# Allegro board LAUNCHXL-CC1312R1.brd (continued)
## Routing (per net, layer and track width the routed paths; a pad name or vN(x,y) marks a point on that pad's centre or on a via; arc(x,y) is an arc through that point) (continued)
VBUS_DET: length 7.3
  TOP w0.15: R116.1 R115.1 10.14,83.85 9.65,84.34 v1(9.65,84.9) ; v1(9.65,89) U5.12
  BOTTOM w0.15: v1(9.65,84.9) v1(9.65,89)
VDD_SWITCH: length 93.7
  TOP w0.15: 35.85,111.8 35.6,111.55 v1(35.6,110.7) ; 35.85,111.8 35.7,111.95 U25.1 ; 35.85,111.8 C145.1
  TOP w0.201: U24.14 43.4,106.95 C144.1
  TOP w0.3: U27.5 4.19,86.32 4.46,86.05 v1(5,86.05) R136.1 ; U26.1 35.57,115.95 36.27,115.25 ; v1(35.67,115.1) 35.82,115.25 36.27,115.25 ; 36.27,115.25 C146.1 ; v1(44,106.3) 43.85,106.45 43.85,106.5 C144.1
  L3 w0.3: v1(35.67,115.1) 36.15,115.1 36.9,114.35 37.9,114.35 38.83,113.42 38.83,111.65 37.88,110.7 v1(35.6,110.7) 35.6,111.55 35.25,111.9 29.79,111.9 26.44,115.25 8.78,115.25 7.43,113.9 6.45,113.9 0.99,108.44 0.99,94.79 1.31,94.47 1.31,92.2 0.99,91.88 0.99,90.06 v1(5,86.05)
  BOTTOM w0.3: v1(35.6,110.7) 42.55,110.7 44,109.25 v1(44,106.3)
VDDC: length 15.8
  TOP w0.2: U5.87 8.85,96.95 6.5,94.6 U5.115 2.45,94.6 C43.1 C44.1 C45.1
VDDR: length 7.1
  TOP w0.3: v1(24.15,48.3) C481.1 24.2,48.95 24.8,48.95 25.3,49.45 U1.48 ; v1(24.15,50.38) 24.15,50.65 C451.1 U1.45
  TOP w0.7: L331.2 28.82,59.9 28.47,60.25 C331.1
  vias: v1(26.03,61.25) v1(26.75,61.2) v1(27.47,61.2)
VDDS: length 13.8
  TOP w0.15: R351.2 v1(23.87,55.48)
  TOP w0.3: U1.22 C222.1 33.86,53.95 34.31,54.4 34.31,54.56 34.67,54.92 C221.1 34.92,55.45 v1(35.25,55.45) ; v1(33.35,48.85) 34.15,48.85 C131.1 C132.1 U1.13 ; U1.34 27.67,56.9 C342.1 C341.1 v1(25.3,57.15) ; FL1.1 24.15,57.4 24.3,57.25 v1(24.3,57.2) ; U1.44 25.14,51.45 24.99,51.6 24.45,51.6 C441.1 24.45,51.8 v1(24.02,52.22)
  vias: v1(23.65,57.1) v1(24.8,56.85)
BP_RESET: length 20.3
  TOP w0.15: R52.1 42.57,69.5 43.27,68.8 46.95,68.8 48.35,67.4 48.35,60.1 48.7,59.75 49.75,59.75 50.6,58.9 50.6,56.83 J2.11
CAL_VDD: length 17.6
  TOP w0.201: U24.2 42.05,107.25 42,107.2 42,107.2 41.85,107.05 41.7,107.05 v1(41.6,106.95) ; U24.4 41.25,107.3 41.3,107.25 41.3,107.2 41.45,107.05 41.48,107.05 41.58,106.95 v1(41.6,106.95) ; U24.9 41.25,106.25 41.65,106.64 41.65,106.88 41.6,106.93 v1(41.6,106.95)
  TOP w0.3: U26.2 35.8,116.45 v1(36.25,116)
  L3 w0.3: v1(41.6,106.95) 41.26,107.29 41.26,114.18 39.44,116 v1(36.25,116)
DCDC_SW: length 2.1
  TOP w0.3: L331.1 28.17,56.85 U1.33
DIO1: length 25.9
  TOP w0.15: v1(30.17,47.2) 29.89,47.49 29.71,47.49 29.17,48.02 U1.6
  BOTTOM w0.15: v1(30.17,47.2) 28.57,48.8 26.9,48.8 26.25,49.45 24.75,49.45 24.05,48.75 20.95,48.75 20.6,48.4 15.14,48.4 12.34,45.6 J1.20
DIO4_SCL: length 110.6
  TOP w0.15: R2.1 5,45.55 5,46.81 J1.17 5.3,48.14 3.15,50.29 3.15,69.05 9.6,75.5 25.65,75.5 34.45,66.7 45.77,66.7 46.16,66.31 46.16,51.54 42,47.37 31.63,47.37 30.67,48.32 U1.9
DIO5_SDA: length 110
  TOP w0.15: U1.10 31.17,48.33 31.83,47.67 41.87,47.67 45.75,51.55 45.75,66.25 45.6,66.4 34.15,66.4 25.35,75.2 9.72,75.2 3.45,68.93 3.45,51.5 5.55,49.4 7,49.4 7.65,48.75 7.65,46.92 J1.19 4.37,43.64 4.29,43.64 R3.1
DIO6_RLED: length 81.8
  TOP w0.15: v1(45.32,65.3) 45.32,64.9 45.38,64.85 45.38,51.6 41.75,47.97 32.03,47.97 31.67,48.33 U1.11 ; v1(30.01,65.53) v1(24.11,65.53)
  L3 w0.15: v1(30.01,65.53) 29.72,65.25 29.72,63.59 29.97,63.35 34.87,63.35 36.32,64.8 41.12,64.8 41.62,65.3 v1(45.32,65.3) 45.94,65.92 J2.3 ; v1(24.11,65.53) 22.98,65.53 18.93,61.48 18.93,54.22 15.59,50.88 P6.2
DIO7_GLED: length 77.2
  TOP w0.15: v1(24.1,64.1) 29.86,64.1 v1(30.15,63.81) ; v1(44.8,65.9) 44.8,64.95 45.07,64.68 45.07,51.72 41.62,48.27 33,48.27 32.53,48.75 U1.12
  L3 w0.15: v1(30.15,63.81) 33.71,63.81 35.79,65.9 v1(44.8,65.9) 47.36,68.46 J2.1 ; P6.4 18.13,51.55 19.95,53.37 19.95,61.07 22.98,64.1 v1(24.1,64.1)
DIO8_MISO: length 35.9
  TOP w0.15: v1(46.63,41.1) 46.6,41.07 44.75,41.07 44.35,40.68 U4.2 ; U1.14 v1(42.44,49.95) v1(44.65,52.16)
  L3 w0.15: v1(44.65,52.16) 47.04,54.55 50.74,54.55 J2.14 ; v1(46.63,41.1) 47.41,41.88 47.41,45.18 42.64,49.95 v1(42.44,49.95)
DIO9_MOSI: length 35.3
  TOP w0.15: U4.5 45.35,43.15 v1(45.5,43.3) ; U1.15 v1(40.99,50.45) 42.2,50.45 44.65,52.9 v1(44.65,57.05)
  L3 w0.15: J2.12 50.78,57.05 v1(44.65,57.05) ; v1(45.5,43.3) 45.87,43.67 45.87,45.75 45.07,46.55 44.52,46.55 40.99,50.08 v1(40.99,50.45)
DIO10_SCLK: length 98.7
  TOP w0.15: J1.13 4.05,55.5 4.05,68.68 8.22,72.85 10.9,72.85 12.95,74.9 25.22,74.9 34.02,66.1 43.3,66.1 44.5,64.9 44.5,57.6 44.22,57.32 44.22,52.93 42.25,50.95 v1(39.83,50.95) U1.16 ; U4.6 v1(44.85,44.25)
  L3 w0.15: v1(44.85,44.25) 44.85,45.37 43.92,46.3 43.1,46.3 39.83,49.57 v1(39.83,50.95)
DIO11_CS: length 29.4
  TOP w0.15: v1(43.85,62.25) 43.85,53.3 42,51.45 U1.17
  L3 w0.15: v1(43.85,62.25) 50.94,62.25 J2.6
DIO12: length 31.3
  TOP w0.15: U1.18 41.9,51.95 43.35,53.4 43.35,64.25 v1(43.8,64.7)
  L3 w0.15: J2.4 51.02,65.92 49.8,64.7 v1(43.8,64.7)
DIO13_BTN1: length 73.9
  TOP w0.15: U1.19 41.6,52.45 v1(42.5,53.35) 43,53.85 43,65.45 42.65,65.8 33.9,65.8 25.85,73.85 15.23,73.85 v1(14.71,73.32) ; R56.2 6.72,73.5 v1(7.27,74.05)
  L3 w0.15: v1(7.27,74.05) 7.67,74.05 7.76,74.13 13.92,74.13 14.42,73.63 14.42,73.61 v1(14.71,73.32) ; v1(42.5,53.35) 44.35,51.5 45.28,51.5 45.73,51.95 50.8,51.95 J2.16
DIO14_BTN2: length 46
  TOP w0.15: J2.18 54.39,48.14 55.85,49.6 55.85,69.19 56.41,69.75 R55.2 ; U1.20 v1(41.43,52.95)
  L3 w0.15: J2.18 50.76,49.45 45.52,49.45 42.02,52.95 v1(41.43,52.95)
DIO15: length 22.5
  TOP w0.15: U1.21 v1(40.15,53.45)
  L3 w0.15: v1(40.15,53.45) 42.82,50.78 43.39,50.78 46.31,47.86 46.31,47.85 47.07,47.85 47.07,47.85 48.03,46.9 50.77,46.9 J2.20
DIO16_TDO: length 50.4
  TOP w0.15: U1.26 31.67,64.82 31.67,64.83 v1(31.67,65.45) ; CR8.5 v1(42.14,75.9) 43.19,76.95 P5.6 43.19,78.93 42.82,79.3 v1(38.9,79.3) ; v1(36.67,71.7) 36.67,70.97 R48.2
  L3 w0.15: v1(31.67,65.45) 31.67,65.85 31.67,65.86 31.67,69.5 33.03,70.85 35.82,70.85 v1(36.67,71.7) ; v1(38.9,79.3) 38.4,79.3 37.9,79.8 32.91,79.8 P4.6
  BOTTOM w0.15: v1(36.67,71.7) 38.07,70.3 41.1,70.3 42.14,71.34 42.14,73.81 42.12,73.82 42.12,74.18 42.14,74.19 v1(42.14,75.9)
DIO17_TDI: length 41.1
  TOP w0.15: U1.27 v1(31.17,66.3) ; P5.8 44.46,75.71 43.3,74.55 39.55,74.55 39.4,74.4 CR8.3 39.05,73.45 v1(38.95,73.35) ; P4.4 34.27,72.68 v1(35.2,71.75) R49.2
  L3 w0.15: v1(31.17,66.3) 31.17,70.92 32.01,71.75 v1(35.2,71.75) 35.85,72.4 37.55,72.4 38.5,73.35 v1(38.95,73.35)
DIO19_CTS: length 25
  TOP w0.15: v1(30.17,60.79) U1.29
  L3 w0.15: J2.7 48.5,60.84 47.94,61.4 30.76,61.4 30.46,61.1 30.46,61.08 v1(30.17,60.79)
DIO20_FLASH_CS: length 61.5
  TOP w0.15: v1(42.5,40.85) 42.7,41.05 R11.1 43.5,41.05 43.85,40.7 U4.1 ; U1.30 29.67,56.73 29.85,56.91 29.85,60.25 29.63,60.47 v1(29.63,61.75)
  L3 w0.15: J2.5 48.5,63.38 48.02,62.9 30.78,62.9 v1(29.63,61.75) 29.63,61.35 29.75,61.23 29.75,58.63 29.93,58.45 36.9,58.45 37.39,57.96 37.39,50.38 42.27,45.5 43.35,45.5 43.91,44.94 43.91,41.34 43.42,40.85 v1(42.5,40.85)
DIO21: length 61.8
  TOP w0.15: J1.15 3.75,53.26 3.75,68.8 8.3,73.35 v1(10.7,73.35) ; U1.31 29.17,56.52 v1(29.23,56.57)
  L3 w0.15: v1(24.5,71.8) 25.3,71.8 29.2,67.89 29.2,61.34 29.38,61.16 29.38,57.13 29.23,56.98 v1(29.23,56.57)
  BOTTOM w0.15: v1(10.7,73.35) 12.95,71.1 23.8,71.1 v1(24.5,71.8)
DIO22: length 51.4
  TOP w0.15: U1.32 v1(28.67,56.47) ; J1.9 4.35,60.28 4.35,68.55 8.2,72.4 v1(9.95,72.4)
  L3 w0.15: v1(25.2,71.19) 25.66,70.74 25.66,70.74 25.88,70.51 25.88,70.5 28.75,67.64 28.75,61.29 28.61,61.16 28.61,60.84 28.67,60.78 v1(28.67,56.47)
  BOTTOM w0.15: v1(9.95,72.4) 11.55,70.8 24.81,70.8 v1(25.2,71.19)
DIO23_ANALOG: length 25.3
  TOP w0.15: U1.36 25.35,55.65 24.5,54.8 19.55,54.8 v1(10.15,64.2)
  L3 w0.15: v1(10.15,64.2) 9.86,64.49 7.77,64.49 J1.3
DIO24_ANALOG: length 20.4
  TOP w0.15: U1.37 25.12,54.95 24.67,54.5 18.42,54.5 18.32,54.6 v1(18.3,54.6)
  L3 w0.15: v1(18.3,54.6) 7.49,54.6 J1.11
DIO25_ANALOG: length 21.2
  TOP w0.15: J1.6 9.6,62.65 9.6,62.4 17.82,54.18 24.97,54.18 25.25,54.45 U1.38
DIO26_ANALOG: length 20
  TOP w0.15: U1.39 25.32,53.95 25.22,53.85 16.35,53.85 10.09,60.11 9.6,60.11 J1.8
DIO27_ANALOG: length 19.1
  TOP w0.15: J1.10 9.9,58.3 14.65,53.55 25.22,53.55 25.32,53.45 U1.40
DIO28_ANALOG: length 18.3
  TOP w0.15: J1.12 10.99,55.76 13.5,53.25 24.79,53.25 25.09,52.95 U1.41
DIO29_ANALOG: length 17.4
  TOP w0.15: U1.42 25.17,52.45 24.67,52.95 10.17,52.95 9.9,53.22 J1.14
DIO30_ANALOG: length 18.2
  TOP w0.15: U1.43 25.24,51.95 24.54,52.65 14.85,52.65 12.88,50.68 J1.16
ET_1V8: length 1.7
  TOP w0.15: 53.35,100.3 TP6.1 52.5,101.15
ET_3V3: length 32.5
  TOP w0.15: v1(55.43,97.55) 55.48,97.6 TP1.1
  TOP w0.3: L23.1 30.7,109.15 30.15,108.6 30.15,108.32 29.47,107.65 ; U14.2 56.35,88.12 57.15,87.32 57.15,83.74 56.85,83.44 54.3,83.44 54,83.74 C70.1 54,86.2 53.55,86.65 v1(53.55,88.6) ; 29.47,107.65 30.55,107.65 v1(30.85,107.95) ; 29.47,107.65 C125.1 28.4,107.65 27.35,108.7 C124.1 27.19,109.25 26.74,109.7 C123.1 ; C123.1 26.6,109.87 26.15,110.32 U20.13 ; C123.1 26.8,109.9 U20.14 ; C123.1 R103.1 26.58,108.82 C126.2 ; 30.65,90.3 30.6,90.35 C107.2 R96.2 32.11,90.68 32.42,90.99 32.42,91.62 U19.6 U19.5 ; 30.65,90.3 v1(30.05,90.3) ; 30.65,90.3 Q2.2
  vias: v1(54.9,97.55)
ET_+12V: length 14.8
  TOP w0.3: v1(52.64,114.41) 52.64,114.89 52.65,114.9 C63.1 C65.1 51.83,115.98 U12.7 ; U13.7 56.58,111.94 C68.1 56.6,111.28 56.4,111.08 v1(56.4,110.6)
  L3 w0.15: TP4.1 52.8,109.35 ; TP4.1 51.95,108.5 ; TP4.1 51.1,109.35 ; TP4.1 51.95,110.2
  L3 w0.3: 54.01,110.6 v1(56.4,110.6) ; v1(52.64,114.41) 52.64,111.74 ; 52.45,110.86 52.44,110.87
  vias: v1(36.45,108.35) v1(36.9,108.05) v1(37.25,108.3)
ET_-12V: length 6.8
  TOP w0.3: 45.19,111.74 45.13,111.8 v1(44.5,111.8) ; 45.19,111.74 C64.2 45.19,112.5 U12.4 ; 45.19,111.74 C66.2 ; U13.4 C69.2 v1(49.57,111.35) 48.83,111.35 48.38,111.8 TP2.1
  vias: v1(40.22,102.64) v1(40.65,102.95)
ET_AVDD: length 3.5
  TOP w0.15: U16.6 49.57,104.5 49.45,104.62 49.45,106.55 49.7,106.8 R93.1
  vias: v1(49.9,98.85) v1(50.7,97.5) v1(51.45,98.6) v1(52.1,98.75) v1(53.12,104.4)
ET_CAL0: length 35.8
  TOP w0.15: U24.13 42.95,106.2 v1(42.95,106.05) ; U5.74 14.05,102.56 15.15,101.46 v1(15.15,100.15) ; R126.1 37.18,105.3 37.03,105.45 v1(37.03,106.03)
  BOTTOM w0.15: v1(42.95,106.05) 42.55,106.05 42.53,106.03 v1(37.03,106.03) 27.91,106.03 22.3,100.43 16.97,100.43 16.7,100.15 v1(15.15,100.15)
ET_CAL1: length 32.2
  TOP w0.15: v1(16.15,100.57) 15.86,100.86 15.86,101.18 14.45,102.59 U5.73 ; v1(40.45,108) 40.75,107.7 U24.5 R127.1
  BOTTOM w0.15: v1(40.45,108) 39.9,108 39.3,107.4 28.85,107.4 22.17,100.73 16.7,100.73 16.55,100.57 v1(16.15,100.57)
ET_CAL2: length 38.8
  TOP w0.15: U5.23 14.05,89.2 15.85,91 v1(15.85,93.8) ; U24.6 v1(40.15,107.5) 39.95,107.7 R129.1
  L3 w0.15: v1(38.49,105.29) 40.15,106.95 v1(40.15,107.5)
  BOTTOM w0.15: v1(38.49,105.29) 38.09,105.29 37.95,105.15 29.62,105.15 23.07,98.6 21.05,98.6 16.25,93.8 v1(15.85,93.8)
ET_CALIBRATE: length 34.8
  TOP w0.15: U5.77 12.85,104.25 12.7,104.4 v1(12.7,104.43) ; U26.4 v1(36.1,117.45)
  BOTTOM w0.15: v1(12.7,104.43) 12.7,106.95 15.1,109.35 15.1,110.57 TP15.1 15.83,114.48 16.3,114.95 19.95,114.95 20.9,115.9 21.85,115.9 22.96,117.01 35.66,117.01 v1(36.1,117.45)
ET_DVDD: length 7.7
  TOP w0.15: R106.2 34.36,109.8 33.97,109.41 33.97,109.39 33.73,109.15 L23.2 ; v1(47.65,105.6) 47.55,105.7 U16.12
  TOP w0.3: R110.1 45.9,99.05 C97.1 ; R110.1 C98.1 46.6,97.7 v1(46.6,96.7) ; R110.1 U16.27
  vias: v1(30.15,105.61) v1(31.85,106.5)
ET_PM2: length 41.3
  TOP w0.15: R106.1 35.75,109.8 v1(36.1,110.15) ; v1(45.2,105.5) U16.17 ; 13.25,103.3 v1(13.25,102.1)
  BOTTOM w0.15: v1(13.25,102.1) 14.32,101.02 22.05,101.02 31.17,110.15 v1(36.1,110.15) 37.15,110.15 38.72,108.57 41.12,108.57 44.2,105.5 v1(45.2,105.5)
ET_PN3: length 55.9
  TOP w0.15: U16.28 v1(47.05,99.5) 47.05,99.47 47.07,99.45 47.07,99.44 47.46,99.05 R110.2 ; v1(5.15,96.6) U5.110
  BOTTOM w0.15: v1(5.15,96.6) 4.05,95.5 4.05,91.45 5.1,90.4 8.3,90.4 8.88,90.98 23.1,90.98 29.88,97.75 45.3,97.75 v1(47.05,99.5)
ET_SSICLK: length 50.2
  TOP w0.15: v1(8.15,91.28) 7.62,91.28 5.88,93.02 5.15,93.02 4.72,92.6 U5.120 ; U16.22 44.9,103 v1(45.25,102.65)
  BOTTOM w0.15: v1(8.15,91.28) 22.98,91.28 29.75,98.05 43.75,98.05 44.45,98.75 44.45,101.85 v1(45.25,102.65)
ET_SSIDAT0: length 48.2
  TOP w0.15: v1(45.35,103.5) U16.21 ; v1(6.85,91.1) 6.55,91.4 U5.123
  BOTTOM w0.15: v1(6.85,91.1) 7.5,91.75 15.55,91.75 21.41,97.61 23.36,97.61 29.4,103.65 44.8,103.65 44.95,103.5 v1(45.35,103.5)
ET_SSIDAT1: length 49
  TOP w0.15: 3.75,91 4.7,91 5.15,91 5.3,90.85 v1(5.7,90.85) ; U16.20 45.2,104 v1(45.3,104.1)
  BOTTOM w0.15: v1(45.3,104.1) 42.9,104.1 42.49,104.5 29.83,104.5 23.24,97.91 21.29,97.91 15.43,92.05 6.3,92.05 5.7,91.45 v1(5.7,90.85)
ET_SSIFSS: length 45.9
  TOP w0.15: v1(42.85,104.85) 43.2,104.5 U16.19 ; U5.121 4.75,92.2 4.86,92.31 5.16,92.31 v1(5.45,92.6)
  BOTTOM w0.15: v1(42.85,104.85) 29.75,104.85 23.11,98.21 21.16,98.21 15.3,92.35 6.37,92.35 6.12,92.6 v1(5.45,92.6)
IRSTN: length 24.7
  TOP w0.15: R20.2 19.9,104.79 v1(19.69,105)
  BOTTOM w0.15: v1(19.69,105) 18.49,103.8 11.95,103.8 9.42,106.32 9.42,109.57 8.72,110.27 6.02,110.27 4.05,108.3 4.05,106.93 P8.10
ITCK: length 11.5
  TOP w0.15: U5.100 2.85,100.6 v1(1.75,101.7)
  BOTTOM w0.15: P8.4 1.05,109.01 1.05,102.4 v1(1.75,101.7)
ITDI: length 13.9
  TOP w0.15: U5.98 2.9,101.4 2.73,101.57 2.73,102.42 v1(2.45,102.7)
  L3 w0.15: v1(5.31,110.4) 4.51,109.6 4.51,104.76 v1(2.45,102.7)
  BOTTOM w0.15: v1(5.31,110.4) 4.08,109.17 3.75,109.17 P8.8
ITDO: length 16.6
  TOP w0.15: v1(2.65,112.85) 2.05,113.45 1.35,113.45 0.85,112.95 0.85,105.1 3.23,102.72 3.23,102.12 3.55,101.8 U5.97
  BOTTOM w0.15: P8.6 2.65,111.95 v1(2.65,112.85)
ITMS: length 8.3
  TOP w0.15: 3.75,101 2.88,101 2.27,101.6 2.27,102.22 v1(1.81,102.69)
  BOTTOM w0.15: P8.2 1.35,106.77 1.35,103.15 v1(1.81,102.69)
LP_RESET: length 22.4
  TOP w0.15: J2.10 53.25,58.3 53.8,58.85 53.8,69.15 53.25,69.7 44.85,69.7 44.65,69.5 R51.1
REF5025: length 27.5
  TOP w0.15: R79.1 52.1,93.9 R81.1 51.85,94.11 v1(51.71,94.25) ; v1(50.65,108.4) C90.1 49.05,108.25 U16.9 ; TP8.1 48.2,96.05 v1(48.85,95.4) R80.1
  BOTTOM w0.15: v1(51.71,94.25) 50,94.25 v1(48.85,95.4) 51.3,95.4 53.35,97.45 53.35,100.8 52.2,101.95 52.2,106.85 v1(50.65,108.4)
RX_TX: length 2.7
  TOP w0.2: L32.2 27.96,47.36 27.96,48 27.67,48.29 U1.3
  TOP w0.3: C31.1 28.32,46.33 L32.2
SENSE_R_BYPASS: length 37.3
  TOP w0.15: U5.78 12.45,102 12.8,101.65 v1(14.3,101.65) ; 30.99,113.1 30.63,113.46 30.63,114.73 30.85,114.95 TP14.1 ; 30.99,113.1 30.2,113.1 v1(29.9,112.8) ; 30.99,113.1 31.14,112.95 U25.8 ; v1(35.1,114.55) 35.65,114.55 35.8,114.4 35.8,113.7 35.55,113.45 U25.4
  L3 w0.15: v1(35.1,114.55) 34.75,114.2 32.4,114.2 TP14.1
  BOTTOM w0.15: v1(29.9,112.8) 29.9,109.3 23.75,103.15 22.3,103.15 20.55,101.4 14.95,101.4 14.7,101.65 v1(14.3,101.65)
TARGET_VDD: length 9.7
  TOP w0.15: v1(37.03,118.05) 36.63,118.05 36.48,117.9 35.35,117.9 U26.5 35.57,117.95 36.02,118.4 v1(36.25,118.4)
  L3 w0.15: 16.49,80.08 16.49,80.35 ; 15.63,80.3 P4.17 17.35,82.02 ; 17.57,81.16 17.39,81.16 ; 15.42,81.16 15.67,81.16
  L3 w0.7: 15.67,81.16 P4.17 ; P4.17 16.49,80.35 ; P4.17 16.49,82.24 ; P4.17 17.39,81.16
USB1V8: length 12.8
  TOP w0.15: U15.26 13.31,106.6 13.4,106.51 ; C85.2 14.8,106.32 v1(14.48,106.65) 13.54,106.65 13.4,106.51 ; 13.4,106.51 C83.1 ; C84.1 v1(6.7,106.6) U15.15
  L3 w0.15: v1(6.7,106.6) 6.98,106.31 7.08,106.31 7.3,106.1 13.46,106.1 14.01,106.65 v1(14.48,106.65)
USB_VBUS: length 61.5
  TOP w0.15: R115.2 v1(11.4,83.85)
  TOP w0.3: 10.08,112.33 R82.2 ; 10.08,112.33 10.14,112.39 CR6.6 ; 10.08,112.33 10.05,112.36 10.05,112.59 ; 10.05,112.59 J6.1 ; 10.05,112.59 v1(8.91,112.59) 8.53,112.97 8.17,112.97 7.4,112.2 C77.1
  TOP w0.5: Q1.2 24.15,107.77 R86.2 24.77,107.15 ; 24.77,107.15 24.72,107.1 23.2,107.1 23.15,107.05 C82.1 ; 24.77,107.15 v1(24.83,107.15)
  L3 w0.15: 20.95,107.63 21.23,107.35 21.23,104.77 23.23,102.77 23.23,92.84 18,87.61
  L3 w0.201: 18,87.61 18,87.03 17.08,86.11 17.08,86.11 16.84,85.87 14.82,83.85 v1(11.4,83.85)
  L3 w0.5: v1(24.83,107.15) 23.27,107.15 22.67,107.75 21.07,107.75 20.95,107.63 17.97,107.63 11.95,113.65 9.97,113.65 v1(8.91,112.59)
USBCLK: length 7.9
  TOP w0.15: U15.14 5.03,107.1 4.55,106.62 4.55,105.6 5.5,104.65 6.45,104.65 6.85,104.25 U5.92
USBD0: length 2.2
  TOP w0.15: U5.81 11.25,104.35 11.6,104.7 U15.24
USBD1: length 2.2
  TOP w0.15: U15.23 11.1,104.62 10.85,104.37 U5.82
USBD2: length 2.2
  TOP w0.15: U5.83 10.45,104.4 10.6,104.55 U15.22
USBD3: length 2.1
  TOP w0.15: U15.21 10.1,104.55 10.05,104.5 U5.84
USBD4: length 2.1
  TOP w0.15: U5.85 9.65,104.5 9.6,104.55 U15.20
USBD5: length 2.2
  TOP w0.15: U15.19 9.1,104.55 9.25,104.4 U5.86
USBD6: length 11.6
  TOP w0.15: U5.106 7.75,98.2 8.05,98.5 v1(8.05,100.5) ; v1(8.6,104.55) U15.18
  BOTTOM w0.15: v1(8.6,104.55) 8.6,101.05 v1(8.05,100.5)
USBD7: length 10.8
  TOP w0.15: v1(7.67,104.55) 7.95,104.55 8.1,104.7 U15.17 ; U5.105 6.15,98.6 6.15,98.6 6.75,98.6 v1(7.05,98.9)
  BOTTOM w0.15: v1(7.05,98.9) 7.05,100 6.75,100.3 6.75,103.63 v1(7.67,104.55)
USBDIR: length 12.6
  TOP w0.15: v1(6.33,108.07) 6.37,108.07 6.4,108.1 U15.12 ; U5.104 5.42,99 5.45,99.03 v1(5.85,99.03)
  BOTTOM w0.15: v1(6.33,108.07) 5.62,107.37 5.62,100.52 5.85,100.3 v1(5.85,99.03)
USBDM: length 7.2
  TOP w0.15: U15.8 7.75,110.3 7.6,110.45 v1(7.6,110.95) ; 10.8,113 10.7,113.1 J6.2 ; 10.8,113 11.25,112.55 CR6.5 ; 10.8,113 v1(10.8,113)
  L3 w0.15: v1(7.6,110.95) 7.6,111.35 8.3,112.05 9.44,112.05 10.39,113 v1(10.8,113)
USBDP: length 6.7
  TOP w0.15: J6.3 11.35,113.24 v1(11.59,113) 11.75,112.84 11.75,112.39 ; v1(8.3,111.05) 8.6,110.75 U15.7
  L3 w0.15: v1(11.59,113) 10.81,112.23 10.27,112.23 9.6,111.55 8.8,111.55 v1(8.3,111.05)
USBID: length 5.3
  TOP w0.15: J6.4 12,113.32 12.8,112.52 12.8,111.25 12.55,111 11.65,111 11.25,111.4 CR6.2
USBNXT: length 14.3
  TOP w0.15: U5.103 5.05,99.4 v1(5.35,99.7) ; U15.11 7.09,108.6 6.39,109.3 v1(5.65,109.3)
  BOTTOM w0.15: v1(5.65,109.3) 4.4,108.05 4.4,100.65 v1(5.35,99.7)
USBSTP: length 5.3
  TOP w0.15: v1(6.65,107.52) 6.67,107.52 6.75,107.6 U15.13 ; U5.91 v1(7.25,105.25)
  BOTTOM w0.15: v1(7.25,105.25) 7.25,106.93 v1(6.65,107.52)
V-SENSE: length 103.2
  TOP w0.15: U10.2 C55.1 v1(25.65,85.1) ; v1(29.65,85.1) C57.1
  TOP w0.201: U25.3 v1(35.75,112.95) ; U25.9 31.03,112.45 30.98,112.5 v1(30.55,112.5) ; U9.2 C57.1
  TOP w0.3: 38.1,86 38.1,86.76 39.24,87.9 45.09,87.9 45.71,87.28 P7.1 46.22,86.53 v1(46.5,86.25) 46.5,85.65 48.25,83.9 48.25,82.76 P10.2 ; 38.1,86 37.67,86 36.42,84.75 30.48,84.75 30.47,84.76 29.99,84.76 v1(29.65,85.1) ; 38.1,86 38.5,85.6 CR7.8 ; v1(21.65,85.1) C53.1 U8.2
  L3 w0.201: v1(35.75,112.95) 31,112.95 v1(30.55,112.5)
  L3 w0.3: v1(21.65,85.1) v1(25.65,85.1) 26.8,85.1 26.8,85.09 27.09,84.8 27.51,84.8 27.8,85.09 27.8,85.1 v1(29.65,85.1)
  BOTTOM w0.3: v1(30.55,112.5) 31.25,111.8 36.06,111.8 36.46,111.4 38.75,111.4 39.85,112.5 42.6,112.5 43.5,113.4 52.1,113.4 53.75,111.75 53.75,90.6 49.4,86.25 v1(46.5,86.25)
VM_SOURCE_VN: length 18.3
  TOP w0.15: R69.2 39.22,116.77 R76.1 ; R76.1 38.85,117.1 TP13.1 ; R76.1 36.24,116.75 v1(36.14,116.85) 36.04,116.95 U26.3
  TOP w0.201: U25.7 31.4,113.45 v1(31.35,113.4)
  L3 w0.3: v1(36.14,116.85) 31.39,116.85 30.67,116.13 30.67,114.08 v1(31.35,113.4)
VM_SOURCE_VP: length 9.4
  TOP w0.15: TP12.1 37.25,112.4 v1(36.7,112.95) 37.6,113.85 R76.2 39.23,113.88 R70.2
  TOP w0.201: U25.2 35.71,112.45 v1(35.8,112.37)
  L3 w0.3: v1(35.8,112.37) 36.28,112.37 36.38,112.46 36.38,112.46 36.7,112.78 v1(36.7,112.95)
WMCU_RESET: length 62
  TOP w0.15: R351.1 26.84,56.4 27.17,56.07 U1.35 ; R351.1 23.22,56.41 22.1,57.54 22.1,70.2 23.45,71.55 v1(23.45,72.15) ; R351.1 23.22,56.39 22.74,55.91 22.59,55.91 22.2,55.51 C351.1 ; CR8.2 38.55,74.03 v1(37.99,73.47) ; P5.10 45.73,75.65 46.55,74.83 46.55,72.46 45.19,71.1 R51.2 R52.2 v1(41.15,71.1)
  L3 w0.15: v1(23.45,72.15) 24.77,73.47 v1(37.99,73.47)
  BOTTOM w0.15: P4.12 24.11,72.81 v1(23.45,72.15) ; v1(37.99,73.47) 38.33,73.81 39.09,73.81 41.15,71.75 v1(41.15,71.1)
WMCU_RXD: length 93
  TOP w0.15: P4.16 19.03,76.32 v1(19.05,76.3) 19.53,75.81 26.63,75.81 35.15,67.3 46.02,67.3 46.81,66.51 46.81,51.34 42.25,46.77 31.23,46.77 30.21,47.78 29.99,47.78 29.67,48.1 U1.7 ; v1(13.71,73.75) 12.75,73.75 10,71 10,68 9.4,67.4 6,67.4 5.05,66.45 5.05,64.66 J1.5
  BOTTOM w0.15: v1(19.05,76.3) 16.5,73.75 v1(13.71,73.75)
WMCU_SWO: length 47.1
  TOP w0.15: P4.2 34.95,76.76 v1(34.95,72.7) ; v1(30.68,66.9) v1(30.68,59.7) 30.67,59.69 U1.28
  L3 w0.15: v1(30.68,66.9) 30.68,72.14 31.24,72.7 v1(34.95,72.7) ; J2.9 48.1,58.3 46.7,59.7 v1(30.68,59.7)
WMCU_TCK: length 46.9
  TOP w0.15: v1(38.11,71.65) 38.11,70.96 R47.2 ; CR8.6 38.55,76.5 38.66,76.61 39.38,76.61 v1(39.67,76.32) 41.29,76.32 41.92,76.95 P5.4 41.92,78.45 41.42,78.95 39.55,78.95 v1(39.25,78.65) ; U1.25 v1(32.17,64.7)
  L3 w0.15: v1(32.17,64.7) 32.17,68.79 33.68,70.3 36.76,70.3 v1(38.11,71.65)
  BOTTOM w0.15: P4.8 30.24,79.67 37.78,79.67 38.8,78.65 v1(39.25,78.65) ; v1(38.11,71.65) 37.2,72.56 37.2,73.85 v1(39.67,76.32)
WMCU_TMS: length 44.9
  TOP w0.15: U1.24 v1(32.88,64.55) ; 37.3,75.9 39.1,77.7 P5.2 ; 37.3,75.9 v1(36.75,75.35) ; 37.3,75.9 CR8.7 ; v1(39.55,71.75) R46.2
  L3 w0.15: v1(32.88,64.55) 32.88,68.59 33.69,69.4 37.2,69.4 v1(39.55,71.75) 39.55,73.62 38.17,75 37.1,75 v1(36.75,75.35)
  BOTTOM w0.15: P4.10 29.92,75.35 v1(36.75,75.35)
WMCU_TXD: length 96.1
  TOP w0.15: v1(23.4,74.35) 12.9,74.35 10.53,71.97 8.2,71.97 4.65,68.43 4.65,62.52 J1.7 ; U1.8 30.17,48.25 31.35,47.07 42.12,47.07 46.51,51.47 46.51,66.38 45.9,67 34.8,67 v1(27.1,74.7)
  L3 w0.15: v1(27.1,74.7) 23.75,74.7 v1(23.4,74.35)
  BOTTOM w0.15: P4.14 21.57,74.81 22.03,74.35 v1(23.4,74.35)
WMCU_VDD: length 35.4
  TOP w0.15: R133.2 41.55,40.45 v1(41.87,40.13) R11.2 43.03,40.1 R59.2 ; 3.3,42.65 v1(2.24,43.7)
  TOP w0.3: FL1.2 v1(24.15,60.1) ; CR8.8 37.35,74.7 37.35,73.4 38.1,72.65 39.25,72.65 39.7,73.1 P5.1 40.65,73.39 v1(40.14,73.9) ; R60.2 43.43,43.67 v1(43.1,44)
  L3 w0.15: 51.19,36.28 P1.1 52.91,36.28 ; 17.35,77.76 P4.18 16,77.51 ; 52.05,36.4 52.05,36.5 ; 48.99,77.76 P10.3 50.71,77.76 ; 7.41,68.46 7.23,68.46 ; 7.19,69.32 J1.1 5.47,67.6 ; 52.79,35.42 53.13,35.42
  L3 w0.7: P1.1 52.05,36.4 ; P1.1 52.79,35.42 53.07,35.7 ; P1.1 51.35,35.42 51.07,35.7 ; P10.3 49.85,77.54 ; P10.3 50.93,78.62 ; P10.3 48.77,78.62 ; 15.63,77.76 P4.18 16.49,77.54 ; 5.05,68.46 J1.1 ; J1.1 6.33,69.54 ; J1.1 7.23,68.46
  vias: v1(23.7,60.55) v1(24.65,60.6) v1(24.7,60.05)
XDS_RESET: length 11.5
  TOP w0.15: U10.1 23.73,84.7 23.46,84.97 U10.6 23.46,87.44 23.35,87.55 v1(23.35,88.02) ; U5.40 21.15,92.2 R58.1 21.25,92.1 21.75,91.6 21.75,90.7 v1(22.75,89.7)
  L3 w0.15: v1(23.35,88.02) 23.74,88.42 23.74,89.4 23.45,89.7 v1(22.75,89.7)
XDS_RESET_LS: length 63.1
  TOP w0.15: P4.11 24.11,82.34 v1(23.7,82.75) 23.46,82.99 U10.15 ; 36.66,84.11 37.15,84.6 CR7.2 ; 36.66,84.11 36.66,83.59 38.32,81.93 40.63,81.93 ; 36.66,84.11 36.54,84.23 v1(34.3,84.23) ; v1(20.83,114.7) 20.98,114.85 21.28,114.85 21.53,114.6 R57.2
  L3 w0.15: v1(23.7,82.75) 24.1,83.15 31.64,83.15 32.71,84.23 v1(34.3,84.23) ; v1(21.66,105.05) 23.53,103.18 23.53,92.69 19.95,89.11 v1(19.95,88.15)
  BOTTOM w0.15: v1(21.66,105.05) 21.66,105.45 21.67,105.47 21.67,106.55 22.35,107.23 22.35,113.18 v1(20.83,114.7) ; v1(19.95,88.15) 20.3,88.5 20.8,88.5 21.12,88.82 21.82,88.82 23.7,86.95 v1(23.7,82.75)
XDS_RX: length 3.1
  TOP w0.15: U5.33 19.15,87.33 18.66,86.84 U8.8
XDS_RX_LS: length 8
  TOP w0.15: U8.13 18.66,83.41 R61.2 18.77,82.45 17.95,81.62 17.95,80.76 18.6,80.11 20.52,80.11 P4.13
XDS_SWO: length 7.2
  TOP w0.15: U8.9 18.05,86.3 18.05,88.75 17.9,88.9 15,88.9 14.85,88.75 U5.25
XDS_SWO_LS: length 25.6
  TOP w0.15: v1(18.1,82.5) 17.77,82.82 17.49,82.82 17.35,82.97 17.35,84.13 17.92,84.7 U8.12 ; 36.45,82.9 35.66,83.69 v1(33.44,83.69) ; 36.45,82.9 R62.2 ; 36.45,82.9 36.81,82.54 P4.1
  L3 w0.15: v1(18.1,82.5) 18.38,82.21 24.04,82.21 24.53,82.7 32.45,82.7 v1(33.44,83.69)
XDS_TCK: length 10.4
  TOP w0.15: U5.35 20.1,90.2 20.65,89.65 v1(20.65,89.2) ; v1(23.25,89.2) 25.34,89.2 27.46,87.08 U9.6
  L3 w0.15: v1(23.25,89.2) v1(20.65,89.2)
XDS_TCK_LS: length 29.3
  TOP w0.15: U9.15 27.46,83.42 27.89,82.99 28.85,82.99 29.19,82.64 P4.7 ; v1(30.65,80.1) 30.95,79.8 43.57,79.8 44.44,80.67 P7.4 44.44,84.2 44.04,84.6 CR7.6
  L3 w0.15: P4.7 29.92,80.43 30.32,80.43 v1(30.65,80.1)
XDS_TDI: length 10.2
  TOP w0.15: U5.38 20.2,91.4 22.85,88.75 25.36,88.75 27.06,87.05 U9.7
XDS_TDI_LS: length 23.7
  TOP w0.15: P7.8 41.9,82.68 41.4,83.18 39.63,83.18 39.53,83.08 38.28,83.08 38.15,83.2 v1(37.75,83.2) CR7.3 ; U9.14 27.06,83.39 28.05,82.4 28.05,80.7 28.64,80.11 29.86,80.11 30.4,80.65 30.4,81.85 31.2,82.65 32.78,82.65 P4.3
  L3 w0.15: P4.3 34.27,82.22 35.25,83.2 v1(37.75,83.2)
XDS_TDO: length 10.1
  TOP w0.15: 19.15,91 20.18,91 22.72,88.45 25.1,88.45 26.25,87.3 26.25,86.1 U9.9
XDS_TDO_LS: length 27.4
  TOP w0.15: CR7.5 v1(40.45,84.1) 42.75,84.1 43.15,83.7 43.15,81.95 P7.6 43.17,81.93 R63.2 ; U9.12 25.92,84.7 25.59,84.37 v1(25.59,82.05)
  L3 w0.15: v1(40.45,84.1) 36.02,84.1 35.72,83.8 34.37,83.8 P4.5 30.61,82.29 26.29,82.29 26.06,82.05 v1(25.59,82.05)
XDS_TMS: length 6.1
  TOP w0.15: U5.36 20.15,90.6 22.66,88.09 U10.8
XDS_TMS_DIR: length 13.5
  TOP w0.15: v1(24.03,87.8) 24.03,87.28 23.86,87.11 U10.5 ; U5.24 14.45,88.85 14.8,89.2 18.02,89.2 18.55,88.68 v1(18.55,87.5)
  L3 w0.15: v1(24.03,87.8) 23.73,87.5 v1(18.55,87.5)
XDS_TMS_LS: length 34.5
  TOP w0.15: CR7.7 v1(39.95,85.1) 44.7,85.1 45.71,84.09 P7.2 46.24,81.93 46.3,81.88 R65.2 ; P4.9 25.59,80.1 23.35,80.1 22.66,80.79 U10.13
  BOTTOM w0.3: P4.9 26.65,83.64 27.61,84.6 33.4,84.6 33.9,85.1 v1(39.95,85.1)
XDS_TX: length 4.5
  TOP w0.15: U8.6 19.46,88.51 20.15,89.2 20.15,89.65 20,89.8 U5.34
XDS_TX_LS: length 3.1
  TOP w0.15: P4.15 19.03,82.28 19.46,82.71 U8.15
XDS_VCC: length 96.4
  TOP w0.15: v1(22.44,102.1) 22.44,101.62 22.31,101.5 R27.1 ; U5.122 5,91.8 5.2,92 v1(5.6,92) ; U5.69 C38.1 v1(16.05,105.08) ; U5.79 12.05,104.48 12.48,104.91 13.1,104.91 v1(13.39,104.62) 13.4,104.63 C6.1 ; C7.1 C42.1 ; C42.1 8.57,85.58 R18.2 v1(8.85,84.9) ; C42.1 8.15,86.46 8.05,86.56 U5.8 ; R33.2 19.03,110.37 C47.1 19.52,109.88 20.35,109.88 20.88,109.35 TP11.1 ; R58.2 21.18,91.18 v1(20.65,91.7) ; C80.1 13.39,109.54 13.75,109.9 v1(13.75,110) ; C80.1 13.04,109.1 U15.31 ; C80.1 13.4,109.44 C79.1 13.2,108.6 U15.30 ; R17.2 19,105.16 v1(18.86,105.3) ; R39.1 22.12,102.67 v1(22.44,102.67) ; v1(6.25,105.1) C78.1 6.72,105.7 7.12,106.1 U15.16 ; U5.101 2.85,100.2 v1(2.55,99.9) ; U10.4 C54.1 ; v1(1.65,95.5) C3.1 ; U15.6 9.1,111.07 v1(9.05,111.12) 9.05,111.16 8.51,111.7 R83.1 ; U8.3 U8.4
  TOP w0.2: U5.28 16.05,87.1 15.45,86.5 ; v1(18.86,105.3) R31.2 ; v1(7.35,102.1) 7.65,102.4 U5.90 ; v1(21.73,97.19) 21.73,96.93 21.65,96.85 C40.1 C39.1 U5.51 U5.52 ; 15.45,86.5 15.25,86.7 U5.26 ; 15.45,86.5 C2.1 v1(15.45,85.85) ; v1(11.45,86.82) 11.25,87.02 U5.16 ; U5.39 20.55,91.8 v1(20.65,91.7) ; C3.1 2.35,95.4 U5.113 4.65,95.4 v1(4.95,95.7) ; 19.15,95 v1(20.21,95) ; U5.7 U5.8 ; U10.3 U10.4
  TOP w0.201: U9.3 28.65,85.5 C56.1 U9.4 ; C6.1 12.6,105.3 12.3,105.6 U15.25
  TOP w0.3: v1(21.7,85.9) C52.1 U8.4 ; C56.1 v1(29.65,85.9) ; C54.1 v1(25.65,85.9) ; v1(2.55,99.9) C4.1
  TOP w0.4: C47.1 17.46,110.35 16.95,110.86 16.95,110.95
  TOP w0.5: U7.3 U7.4 C49.1 16.95,110.95 15.75,109.75 v1(15.75,109)
  L3 w0.3: P10.1 43.42,83.7 41.12,86 30.23,86 30.13,85.9 v1(29.65,85.9) v1(25.65,85.9) v1(21.7,85.9) ; 15.45,85.91 v1(15.45,85.85)
  BOTTOM w0.15: P8.1 1.75,105.35 v1(1.77,105.35)
  BOTTOM w0.3: v1(21.7,85.9) 21.3,86.3 15.84,86.3 15.45,85.91 v1(15.45,85.85)
N949215: length 7.7
  TOP w0.15: v1(19.2,102.5) 19,102.7 R17.1 R20.1 R21.1 ; U5.70 v1(15.65,102.2)
  BOTTOM w0.15: v1(19.2,102.5) 18.91,102.79 16.23,102.79 v1(15.65,102.2)
N949243: length 2.1
  TOP w0.15: U5.60 20.54,100.2 21.04,99.7 R30.1
N949263: length 2.4
  TOP w0.3: R34.2 20,110.38 C47.2 19.97,111.08 R33.1 U7.5
N949375: length 2.3
  TOP w0.15: U5.59 20.06,99.8 21.01,98.85 R28.2
N949687: length 13.6
  TOP w0.15: v1(7.85,101.65) 8.05,101.85 U5.89 ; v1(5.35,108.35) 5.05,108.65 4.2,108.65 3.95,108.4 C1.1
  BOTTOM w0.15: v1(5.35,108.35) 5.66,108.65 6.65,108.65 8.15,107.15 8.15,101.95 v1(7.85,101.65)
N949695: length 21.6
  TOP w0.15: C9.1 1.85,110.2 Y3.1 2.5,110.75 3.52,109.73 v1(6.15,109.73) ; U5.88 8.45,101.65 7.45,100.65 v1(7.2,100.65)
  BOTTOM w0.15: v1(7.2,100.65) 7.77,100.07 8.23,100.07 9.05,100.9 9.05,104.7 9.02,104.73 9.02,104.73 8.78,104.98 8.77,104.98 8.57,105.18 8.57,107.73 6.6,109.7 6.58,109.7 6.55,109.73 v1(6.15,109.73)
N950083: length 5.9
  TOP w0.15: U5.9 8.45,86.9 R18.1 C8.1 C50.1 9.85,85.6 10.45,85 U6.3
N951001: length 2.2
  TOP w0.15: U5.63 19.91,101.4 20.91,102.4 R39.2
N951013: length 1.9
  TOP w0.15: U5.61 R29.1
N951017: length 2
  TOP w0.15: 19.15,101 20.41,101 20.91,101.5 R27.2
N952443: length 2.4
  TOP w0.2: U5.68 16.45,104.05 16.85,104.45 C46.1 16.85,104.8 R31.1
N1004371: length 6.6
  TOP w0.15: R23.2 0.95,88.26 1.46,87.75 3.9,87.75 5.05,88.9 5.76,88.9 6.05,88.61 U5.3
N1004534: length 5.7
  TOP w0.15: R25.2 3.78,88.33 4.66,89.2 6.1,89.2 6.45,88.85 U5.4
N1013277: length 4.3
  TOP w0.15: U1.46 25.17,50.45 24.57,49.85 23.8,49.85 23.14,50.5 22.2,50.5 Y2.3
N1014101: length 10
  TOP w0.15: C41.1 32.4,42.6 Y1.1 31,42.9 30.65,43.25 30.65,43.25 30.29,43.61 30.29,45.99 28.3,47.97 28.3,48.27 28.17,48.39 U1.4
N1014113: length 7.1
  TOP w0.15: U1.5 28.67,48.1 31.37,45.4 Y1.2 32.7,45.4 32.9,45.6 C51.1
N1017630: length 2.3
  TOP w0.3: U4.8 43.38,42.65 43.28,42.75 C30.1 R133.1
N1018952: length 4.5
  TOP w0.15: Y2.1 21.98,48.74 22.98,48.74 23.8,49.55 24.7,49.55 25.1,49.95 U1.47
N1031635: length 6.3
  TOP w0.15: v1(7.75,113.45) 7.75,113.2 7.65,113.3 R32.2 ; CR6.1 v1(10.75,111.2)
  L2 w0.15: v1(7.75,113.45) 7.75,112.5 8.15,112.1 10.25,112.1 10.75,111.6 v1(10.75,111.2)
  vias: v1(7.25,114.6)
N1105722: length 0.9
  TOP w0.15: R15.1 18.12,40.38 CR1.2
N1105771: length 0.9
  TOP w0.15: CR2.2 15.57,40.38 R14.1
N1105824: length 1.6
  TOP w0.15: P6.1 15.59,42.75 15.57,42.73 R14.2
N1106228: length 1.7
  TOP w0.15: P6.3 18.13,42.75 18.12,42.74 R15.2
N1176544: length 23.9
  TOP w0.15: J2.13 48.05,54.7 48.05,67.1 46.65,68.5 40.42,68.5 39.57,69.35 R46.1
N1176548: length 27.7
  TOP w0.15: J2.15 47.75,52.46 47.75,66.97 46.52,68.2 39.27,68.2 38.12,69.35 R47.1
N1176568: length 31.4
  TOP w0.15: R48.1 36.67,69.35 38.12,67.9 46.4,67.9 47.45,66.85 47.45,50.22 J2.17
N1177007: length 35.1
  TOP w0.15: J2.19 47.15,47.98 47.15,66.6 46.15,67.6 36.97,67.6 35.22,69.35 R49.1
N1288065: length 3.5
  TOP w0.15: R55.1 55.49,69.75 54.15,71.09 SW2.3
N1288098: length 1.8
  TOP w0.15: R56.1 5.22,73.5 4.5,72.78 SW1.4
N1384129: length 1.2
  TOP w0.15: SW3.3 22.47,114.43 R57.1
N1409884: length 1.6
  TOP w0.15: R59.1 44.41,39.25 44.85,39.69 U4.3
N1409917: length 0.7
  TOP w0.3: U4.7 R60.1
N1532633: length 4
  TOP w0.15: C60.1 43.15,115.75 43.05,115.85 R69.1 ; C60.1 44.05,115.75 44.28,115.98 U12.2 ; C60.1 C62.2
N1532640: length 3.9
  TOP w0.15: C60.2 44.1,114.83 44.21,114.71 U12.3 ; C60.2 43.15,114.83 43.12,114.8 R70.1 ; C60.2 43.7,114.73 C61.1
N1532863: length 2.8
  TOP w0.15: U12.1 46.34,117.25 47.49,118.4 R71.2
N1532870: length 2.7
  TOP w0.15: R71.1 48.41,118.4 49.55,117.25 U12.8
N1536103: length 11.8
  TOP w0.15: 55.15,105.5 54,106.65 R72.1 C67.1 ; 55.15,105.5 CR9.1 ; 55.15,105.5 TP7.1
  TOP w0.3: CR9.1 53.83,104.08 53.5,104.08 52.9,103.48 52.14,103.48 52.1,103.44 51.36,103.44 51.3,103.5 U16.4
N1536178: length 5.4
  TOP w0.15: U12.6 50.11,114.71 49.25,113.85 TP9.1 49.98,111.57 50.16,111.57 50.45,111.29 U13.3
N1536208: length 4.1
  TOP w0.15: U13.2 51.93,111.94 52.97,112.98 R74.2 R73.2
N1536226: length 6.3
  TOP w0.15: R73.1 54.84,113.65 54.04,112.86 54.04,111.49 54.25,111.29 ; 54.25,111.29 U13.6 ; 54.25,111.29 54,111.04 R72.2
N1540868: length 1.1
  TOP w0.15: U14.5 C71.1
N1541303: length 7.8
  TOP w0.15: R78.2 50.95,92.83 51.54,92.24 51.91,92.24 52.15,92 52.15,90.14 51.4,89.39 U14.6 49.35,89.39 48.6,90.14 R77.2
N1541344: length 3.7
  TOP w0.3: U11.3 50.75,94.25 R78.1 50.22,93.75 49.92,94.05 C73.1
N1541677: length 2.4
  TOP w0.15: C74.1 U11.4 53.84,93.91 R79.2
N1541715: length 6.1
  TOP w0.15: C74.2 53.43,95.97 52.45,96.95 U11.1 51.15,96.95 50.5,96.3 R80.2
N1542217: length 1.4
  TOP w0.15: R81.2 52.72,92.73 C76.1
N1548408: length 1.3
  TOP w0.15: U15.4 10.1,111.31 R82.1
N1553941: length 1.7
  TOP w0.15: R83.2 9.47,111.5 9.47,111.05 9.6,110.93 U15.5
N1559020: length 2.8
  TOP w0.5: R85.2 21.57,107.03 C82.2 21.59,108.14 Q1.1
N1559161: length 5.6
  TOP w0.3: C151.1 22.05,111.75 22.25,111.95
  TOP w0.5: R86.1 23.25,107.9 23.2,107.95 Q1.3 FL2.2 22.25,111.95
N1567630: length 3.2
  TOP w0.15: U15.29 13.2,108.1 C87.1 13.4,108 13.74,108.33 14.52,108.33 14.95,108.76 C86.2
N1579665: length 1.6
  TOP w0.15: U15.32 12.58,109.6 12.82,109.85 12.82,110 13.37,110.55 R84.2
N1580179: length 9.1
  TOP w0.15: R87.2 19.7,108.32 19.5,108.12 17.7,108.12 16.9,108.93 Y4.1 16.07,108.22 C88.2 15.65,108.21 14.89,107.45 13.08,107.45 12.93,107.6 U15.28
N1580186: length 11.9
  TOP w0.15: U15.27 15.05,107.1 15.51,106.63 15.64,106.63 v1(15.92,106.35)
  TOP w0.3: R87.1 C89.2 ; C89.2 20.13,106.4 19.05,106.4 Y4.3 ; C89.2 20.17,106.4 v1(20.75,106.4)
  L3 w0.15: v1(15.92,106.35) 16.21,106.06 20.41,106.06 v1(20.75,106.4)
N1589081: length 1.6
  TOP w0.15: C5.1 51.75,101.95 51.2,102.5 U16.2
N1589096: length 1.4
  TOP w0.15: C92.1 U16.11
N1589103: length 1
  TOP w0.3: C93.1 45.45,100.45 U16.25
N1594429: length 10.3
  TOP w0.15: C96.1 25.85,98.63 26.32,99.1 U17.6 U17.7 U17.8 C147.1 28.2,100.65 Y5.4 29.05,103.63 29.97,104.55 L22.2
N1594693: length 1.4
  TOP w0.15: U17.1 23.85,101.38 Y5.3
N1594702: length 1.3
  TOP w0.3: U16.24 R131.2
N1594966: length 0.5
  TOP w0.15: U17.3 U17.2
N1594995: length 17.8
  TOP w0.15: U17.5 29.3,98.6 v1(31,100.3) ; v1(42.75,100.35) R131.1
  BOTTOM w0.15: v1(31,100.3) 31.7,101 40.44,101 41.09,100.35 v1(42.75,100.35)
N1595900: length 2
  TOP w0.15: U16.7 51.43,105 51.65,105.22 R92.2
N1605224: length 1.4
  TOP w0.15: R93.2 50.72,106.35 50.5,106.12 U16.8
N1605907: length 1.4
  TOP w0.3: R94.2 42.99,102.83 43.32,102.5 U16.23
N1644260: length 2.1
  TOP w0.15: R114.2 5.26,104.4 5.65,104.01 U5.95
N1644363: length 1
  TOP w0.15: U5.96 4.9,103.65 R113.2
N1687235: length 9.5
  TOP w0.15: U19.11 U19.10 34.55,90.7 34.05,90.2 ; 34.05,90.2 v1(33.55,89.7) U19.8 ; 34.05,90.2 U19.9
  TOP w0.3: U19.4 31.6,92.7 C108.1 R96.1 31.75,91.2 v1(31.92,91.2)
  BOTTOM w0.15: v1(33.55,89.7) 33.55,90.1 32.45,91.2 v1(31.92,91.2)
N1687263: length 1.6
  TOP w0.3: Q2.1 33.05,90.1 U19.7
N1687273: length 8.7
  TOP w0.3: L25.1 27.85,90.25 29.67,88.43 29.67,86.98 30.6,86.05 ; C109.2 30.6,86.05 ; 30.6,86.05 30.6,86.07 31.6,87.07 Q2.3
N1687279: length 0.2
  TOP w0.5: 31.2,98.85 31.2,99.1
N1687281: length 5.6
  TOP w0.15: TP5.1 35.5,98.95 CR10.1 ; 33.67,104.08 v1(33.02,104.08)
  L3 w0.15: v1(33.5,102.2) 33.02,102.68 v1(33.02,104.08)
N1687325: length 1.2
  TOP w0.15: C110.1 34.74,95.8 34.55,95.61 U19.21
N1687331: length 1
  TOP w0.3: U19.18 36.79,94.74 C111.1
N1687341: length 4.1
  TOP w0.15: R101.2 C120.1 35.44,96.7 35.29,96.55 R97.2 34.81,96.55 34.05,95.79 U19.22
N1687345: length 0.5
  TOP w0.3: U19.14 U19.13
N1687359: length 25.5
  TOP w0.15: 39.64,94.11 39.66,94.11 TP3.1
  TOP w0.3: v1(36.4,89.75) 36.4,89.27 ; 36.4,89.27 36.62,89.05 ; 36.4,89.27 36.4,89.2 C114.1 ; U19.15 36.77,92.7 37,92.47 37,92.42 R98.2 37.62,92.15 37.95,92.15 v1(38.2,92.4) 38.6,92.8 CR11.2 R100.1 39.25,93.71 41,95.46 v1(41,96.8) C232.1 40.95,98.3 U22.8 ; 36.62,89.05 36.25,89.05 C114.1 ; 36.62,89.05 C119.1 ; v1(37.9,96.75) 37.7,96.95 U22.5 ; C114.1 C117.1
  BOTTOM w0.3: v1(38.2,92.4) 36.4,90.6 v1(36.4,89.75) ; v1(37.9,96.75) 40.47,96.75 40.52,96.8 v1(41,96.8)
N1687363: length 3
  TOP w0.3: U19.16 37.15,93.2 R98.1 ; R99.1 C113.1
  TOP w0.5: R98.1 37.45,93.5 R99.1
N1687373: length 3.3
  TOP w0.3: C112.1 37.65,95.4 R99.2 37.55,94.6 37.03,94.08 37.03,93.95 36.77,93.7 U19.17
N1687391: length 0.8
  TOP w0.3: C113.2 R100.2
N1687461: length 1.5
  TOP w0.15: R102.2 35.17,97.25 35.55,97.62 C120.2
N1687583: length 6.8
  TOP w0.3: v1(27.4,109.9) 27.45,109.95 U20.15 ; v1(27.1,107.1) 26.6,107.6 R103.2 C126.1 25.79,107.84 25.26,107.84 25.05,108.05 R104.1
  BOTTOM w0.3: v1(27.4,109.9) 27.4,107.88 27.1,107.58 v1(27.1,107.1)
N1687761: length 2.6
  TOP w0.3: C135.2 34.18,107.92 R118.2 R117.1 34.97,107.82 U21.2
N1687779: length 1.1
  TOP w0.15: U21.6 34.32,103.68 C137.1
N1687817: length 1.9
  TOP w0.3: C138.1 39.04,96.7 38.59,97.15 38.59,97.16 38.35,97.4 U22.6
N1687829: length 4.1
  TOP w0.3: U22.2 39,103.39 38.55,103.84 R120.2 38.55,104.65 38.77,104.87 C136.2 40.28,104.87 R119.1
N1699637: length 2.5
  TOP w0.201: C141.1 U24.1
  TOP w0.3: C141.1 43.4,108.65 R124.2
N1715528: length 4.6
  TOP w0.201: C142.1 U24.3
  TOP w0.3: C142.1 41.65,109.25 R125.2
N1716003: length 1.8
  TOP w0.15: U24.8 40.4,105.8 40.33,105.88 39.97,105.88 39.95,105.85 C143.1 R128.1
N1936147: length 2.8
  TOP w0.15: R137.2 5.6,85.15 6.03,85.58 6.03,85.59 6.49,86.05 R136.2
  TOP w0.201: U27.4 R137.2
N2070550: length 1.5
  TOP w0.3: C231.1 33.88,54.93 33.4,54.45 U1.23
N2071733: length 2.5
  TOP w0.3: L11.1 C11.1 26.48,47.03 L12.2 26.67,47.9 U1.1
N2072219: length 2.5
  TOP w0.3: C21.1 L32.1 L12.1 27.17,47.93 U1.2
N2075216: length 2.4
  TOP w0.3: 26.9,44.88 26.9,44.93 L11.2 ; 26.9,44.88 C33.1 L33.1 ; 26.9,44.88 C21.2
N2075665: length 1.4
  TOP w0.3: L34.1 C34.1 L33.2
N2076038: length 8.8
  TOP w0.3: L34.2 C35.1
  TOP w0.32: C35.1 26.9,36.82 29.1,34.62 C37.1
N2078765: length 13.6
  TOP w0.32: C37.2 30.04,32.65 30.84,31.85 J7.1
N2082297: length 2.4
  TOP w0.32: Z63.1 Z62.1 Z61.1 Z60.2
N2245591: length 1.3
  TOP w0.32: Z63.2 A1.1
  vias: v1(10.3,11.55) v1(10.35,14.1) v1(10.4,5.95) v1(10.4,1.8) v1(10.45,17.95) v1(11.7,16.35) v1(11.75,4.6) v1(12.19,7.95) v1(12.4,12.9) v1(12.9,3.05) v1(13.45,17.95) v1(14.95,11.6) v1(15.15,6.65) v1(15.1,1.7) v1(17.2,16.55) v1(17.95,13) v1(18.05,8) v1(18.35,3.05) v1(20.15,18) v1(20.55,11.6) v1(20.5,1.7) v1(22.19,6.67) v1(22.7,16.67) v1(23.5,12.95) v1(23.8,3) v1(25.75,8.05) v1(26.15,1.6) v1(26.35,11.6) v1(26.5,18.05) v1(28.4,24.95) v1(28.4,19.7) v1(29.1,12.9) v1(29.75,22.5) v1(29.7,16.65) v1(29.95,6.65) v1(32.45,11.55) v1(32.7,7.95) v1(35.8,13) v1(37.35,6.7) v1(38.7,7.95) v1(39.35,11.67) v1(42.27,6.67) v1(42.6,13.05) v1(44.7,8) v1(45.35,11.67) v1(46.45,9.8) v1(47.65,13) v1(47.75,6.75)
N2266542: length 0.7
  TOP w0.32: C36.2 Z60.1
N10367920: length 0.9
  TOP w0.15: CR5.2 R25.1
N10368080: length 0.9
  TOP w0.15: CR4.2 R23.1
N15411560: length 1.4
  TOP w0.15: C72.1 48.6,88.3 R77.1

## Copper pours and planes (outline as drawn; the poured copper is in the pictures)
5V0 on TOP: 15.75,112.85 15.6,113 15.6,114.45 16.1,114.95 25.35,114.95 26.5,116.1 26.5,117.35 26.15,117.7 26.15,118.2 26.35,118.4 27.55,118.4 27.7,118.25 27.7,115.95 25.2,113.45 22.91,113.45 22.91,112.85
GND on TOP (solid shape): 9.45,79.1 0.95,79.1 0.65,80.1 0.45,81.3 0.45,84.1 9.45,84.1
GND on BOTTOM (solid shape): 9.45,79.1 0.95,79.1 0.65,80.1 0.45,81.3 0.45,84.1 9.45,84.1
GND on TOP: 39.95,39.25 39.95,33.4 44.2,33.4 44.2,26.65 23,26.65 23,39.25
GND on TOP: 0.45,114.1 0.45,117.84 0.73,118.52 1.41,118.8 6.45,118.8 6.45,117.6 6.55,117.6 6.55,114.1
GND on TOP, BOTTOM: 53.25,114.2 53.25,118.8 56.99,118.8 57.67,118.52 57.95,117.84 57.95,114.2
GND on BOTTOM: 0.45,26.55 0.45,68.5 0.71,70 1.44,71.34 2.65,74.7 1.57,78.1 1.5,78.18 1.44,78.26 1.25,78.52 1.07,78.8 0.61,79.91 0.45,81.1 0.45,81.29 0.45,81.3 0.45,117.84 0.73,118.52 1.41,118.8 6.45,118.8 6.45,117.6 8.05,117.6 8.05,115.5 9.95,115.5 9.95,117.6 12.75,117.6 12.75,115.5 14.65,115.5 14.65,117.6 16.25,117.6 16.25,118.8 56.99,118.8 57.67,118.52 57.95,117.84 57.95,117.6 57.95,84.8 57.95,81.1 57.85,80.3 57.79,80 57.81,80 57.48,79.08 56.96,78.26 55.75,74.8 56.96,71.34 57.69,70 57.95,68.5 57.95,26.55 ; 12 cut-outs
GND on BOTTOM: 0.45,114.3 0.45,117.84 0.73,118.52 1.41,118.8 5.05,118.8 5.05,114.3
GND on L2: 0.45,26.55 0.45,68.5 0.71,70 1.44,71.34 2.65,74.8 1.44,78.26 0.92,79.09 0.59,80 0.61,80 0.55,80.3 0.45,81.3 0.45,117.84 0.73,118.52 1.41,118.8 6.45,118.8 6.45,117.6 8.05,117.6 8.05,115.5 9.95,115.5 9.95,117.6 12.75,117.6 12.75,115.5 14.65,115.5 14.65,117.6 16.25,117.6 16.25,118.8 56.99,118.8 57.67,118.52 57.95,117.84 57.95,117.6 57.95,81.3 57.95,81.1 57.85,80.3 57.79,80 57.81,80 57.48,79.08 56.96,78.26 55.75,74.8 56.96,71.34 57.69,70 57.95,68.5 57.95,26.55 ; 2 cut-outs
GND on L3: 0.43,26.54 0.43,68.49 0.68,70 1.42,71.33 2.63,74.79 1.42,78.25 0.9,79.08 0.56,79.99 0.58,79.99 0.52,80.29 0.42,81.29 0.43,117.83 0.71,118.51 1.39,118.79 6.42,118.79 6.42,117.59 8.02,117.59 8.02,115.49 9.93,115.49 9.93,117.59 12.72,117.59 12.72,115.49 14.63,115.49 14.63,117.59 16.23,117.59 16.23,118.79 56.96,118.79 57.64,118.51 57.92,117.83 57.92,117.59 57.93,81.29 57.93,81.09 57.82,80.29 57.76,79.99 57.79,79.99 57.45,79.08 56.93,78.25 55.72,74.79 56.93,71.33 57.67,70 57.92,68.49 57.92,26.54 ; 29 cut-outs
VDDR on TOP: 27.8,59.7 27.8,61.5 25.8,61.5 25.8,60.9 26.8,60.9 26.8,59.7
VDDR on L3: 26.27,48.15 26.27,51.65 23.39,51.65 23.39,57.55 28.31,57.55 28.31,61.65 25.71,61.65 25.71,60.1 25.03,59.55 21.43,59.55 21.43,48.15
VDDS on TOP: 23.45,58.5 23.45,56.65 25,56.65 25,58.5
VDDS on L3: 23.39,57.45 23.39,51.65 26.27,51.65 26.27,48.65 34.67,48.65 34.67,54.6 35.91,54.6 35.91,57.45
(no net) on TOP: 57.69,70.05 57.95,68.55 57.95,39.18 57.95,26.65 44.2,26.65 44.2,33.4 39.95,33.4 39.95,39.25 23,39.25 23,26.65 0.45,26.65 0.45,68.55 0.71,70.05 1.44,71.39 2.65,74.85 1.44,78.31 0.71,79.65 0.45,81.15 0.45,117.89 0.73,118.57 1.41,118.85 6.45,118.85 6.45,117.65 8.05,117.65 8.05,115.55 9.95,115.55 9.95,117.65 12.75,117.65 12.75,115.55 14.65,115.55 14.65,117.65 16.25,117.65 16.25,118.85 56.99,118.85 57.67,118.57 57.95,117.89 57.95,81.15 57.69,79.65 56.96,78.31 55.75,74.85 56.96,71.39 ; 47 cut-outs
ET_1V8 on TOP: 49.8,102.2 52.1,102.2 52.35,102.45 53.15,102.45 53.35,102.25 53.35,100.85 53.55,100.65 54.6,100.65 54.8,100.5 54.8,99.95 54.55,99.7 53.25,99.7 52.35,100.6 50.6,100.6 50.4,100.8 50.4,101.35 50.2,101.55 49.75,101.55 49.65,101.65 49.65,102.05
ET_3V3 on TOP: 53.2,97.4 54.25,97.4 54.5,97.65 54.5,99.2 54.7,99.4 55.5,99.4 55.7,99.2 55.7,97.2 55.25,97.2 55.25,96.4 53.3,96.4 53.1,96.6 53.1,97.3
ET_3V3 on L3: 31.27,110.55 31.27,106.85 27.31,106.85 27.31,94.35 30.07,91.55 50.91,91.55 53.39,94.1 53.39,97.95 55.87,97.95 55.87,90.05 53.47,88.2 26.81,88.2 24.15,90.89 24.15,110.55
ET_+12V on TOP: 34.85,109.05 35.35,109.05 35.85,108.55 38.1,108.55 38.65,108 38.65,106.9 38.5,106.75 37.4,106.75 36.95,107.2 36.1,107.2 35.85,106.95 35.85,106.5 35.8,106.45 35.45,106.45 35.4,106.5 35.4,107.5 35.5,107.6 35.5,108.2 35.35,108.35 34.8,108.35 34.75,108.4 34.75,108.95
ET_+12V on L3: 35.51,109.25 37.59,109.25 37.59,102.6 37.99,102.2 43.03,102.2 43.03,112.15 54.11,112.15 54.11,106.45 45.51,106.45 45.51,99.25 35.51,99.25
ET_-12V on TOP: 38.4,104.45 38.4,105.1 38.5,105.2 39,105.2 39.15,105.05 39.15,104.6 39.25,104.45 40.65,104.45 40.65,103.2 41.9,103.2 42.15,102.95 42.15,101.2 41.85,100.9 41,100.9 40.4,101.5 39.9,101.5 39.4,101.95 39.4,103.45 39.1,103.45 39.1,104.3 38.55,104.3
ET_-12V on L3: 40.12,102.35 39.87,102.6 39.87,104.71 41.47,106.31 41.47,112.2 51.35,112.2 51.35,111.05 43.23,111.05 43.23,102.64 42.94,102.35
ET_AVDD on TOP: 49.75,104.65 50.95,104.65 52,105.7 52,105.85 52.2,106.05 53.45,106.05 53.65,105.85 53.65,104.55 52.75,103.65 52.35,103.65 52.1,103.9 52.1,104.2 52,104.3 49.8,104.3 49.7,104.4 49.7,104.6
ET_AVDD on TOP: 49.2,101.3 49.2,99.8 49.55,99.45 53.75,99.45 54.1,99.1 54.1,98.05 53.9,97.85 52.7,97.85 52.3,97.45 50.95,97.45 50.35,96.85 49.4,96.85 49.1,97.15 49.1,98.4 48.7,98.8 48.7,99.45 48.85,99.6 48.85,101.3
ET_AVDD on L3: 48.51,97.15 48.51,104.65 53.27,104.65 53.27,97.15
ET_DVDD on TOP: 28.2,106.9 29.95,106.9 30.3,107.25 31.95,107.25 32.3,107.6 32.3,109.85 32.5,110.05 33.35,110.05 33.6,109.8 33.6,108.6 33.35,108.35 33,108.35 32.85,108.2 32.85,106.95 31.3,105.4 30.3,105.4 30,105.1 30,104.75 29.8,104.55 28.35,104.55 28.15,104.75 28.15,106.85
ET_DVDD on L3: 28.05,106.75 32.71,106.75 32.71,99.2 45.51,99.2 45.51,106.25 48.67,106.25 48.67,96.4 28.05,96.4
TARGET_VDD on L3: 35.83,116.5 35.83,118.65 51.84,118.65 57.75,112.71 57.75,87.44 55.83,85.9 19.27,85.95 17.79,84.5 17.79,79.95 15.23,79.95 15.23,88.25 53.59,88.25 55.87,90.1 55.9,108.07 47.51,116.5 ; 2 cut-outs
WMCU_VDD on TOP: 23.45,60.95 23.45,58.7 25,58.7 25,60.95
WMCU_VDD on L3: 24.47,61.7 24.47,66.4 15.47,75.2 7.71,75.2 7.71,67.4 4.91,67.4 4.91,42.35 1.19,42.35 1.19,70.6 4.99,70.6 4.99,77.45 15.55,77.45 15.55,79.55 17.55,79.55 17.55,77.45 47.59,77.45 47.59,79.45 51.51,79.45 51.51,77.15 54.87,77.15 54.87,35.3 40.51,35.3 40.51,44.75 43.39,44.75 43.39,43.6 42.15,43.6 42.15,38.55 53.15,38.55 53.15,75.2 41.11,75.2 41.11,73.4 39.71,73.4 39.71,75.2 20.79,75.2 28.19,67.6 28.19,61.8 25.55,61.8 25.55,60.3 24.84,59.75 23.35,59.75 23.35,61.15
XDS_VCC on L3: 7.49,84.1 7.45,84.11 7.42,84.13 6.54,85.01 6.52,85.04 6.51,85.08 6.5,85.21 6.51,85.25 6.52,85.28 6.5,85.75 6.03,85.77 6,85.76 5.96,85.75 5.83,85.76 5.79,85.77 5.76,85.79 4.98,86.57 4.96,86.6 4.95,86.64 4.95,87.1 4.92,87.25 4.83,87.38 0.55,91.71 0.55,108.65 4.45,111.31 14.13,111.3 22.91,102.5 22.91,92.5 16.54,86.09 16.51,86.07 16.47,86.06 16.34,86.05 16.3,86.06 16.27,86.07 15.8,86.05 15.78,85.58 15.79,85.55 15.8,85.51 15.79,85.38 15.78,85.34 15.76,85.31 14.58,84.13 14.55,84.11 14.51,84.1
N1031635 on TOP: 6.75,112.9 6.75,117.6 8.05,117.6 8.05,115.5 9.95,115.5 9.95,117.6 12.75,117.6 12.75,115.7 14.45,115.7 14.45,115.1 14.65,115.1 14.65,115.7 14.65,117.6 15.95,117.6 15.95,112.9 ; 1 cut-out
N1031635 on BOTTOM, L2: 6.75,112.9 6.75,117.6 8.05,117.6 8.05,115.5 9.95,115.5 9.95,117.6 12.75,117.6 12.75,115.5 14.65,115.5 14.65,117.6 15.95,117.6 15.95,112.9
N1687279 on TOP: 26.75,94 32.85,94 33.25,94.4 33.25,95.5 33.1,95.65 31.9,95.65 31.7,95.85 31.7,99.6 31.45,99.85 30.9,99.85 28.5,97.45 25.6,97.45 25.35,97.2 25.35,95.4
N1687281 on TOP: 33.35,94.5 33.45,94.4 33.65,94.4 33.75,94.5 33.75,96 33.9,96.15 34.25,96.15 34.45,96.35 34.45,96.9 34.35,97 34.05,97 34.05,97.6 34.15,97.7 34.75,97.7 34.95,97.9 34.95,101.65 35.91,102.61 35.89,104.55 34.55,104.55 31.95,101.95 31.95,98 32.25,97.7 33.15,97.7 33.35,97.5 33.35,96.9 32.85,96.9 32.7,96.71 32.7,96.31 32.84,96.15 33.35,96.15
N1687345 on TOP: 35.85,91.9 36.8,91.9 37.05,91.65 37.75,91.65 37.9,91.8 37.9,91.85 42.05,91.85 43.25,90.65 44.7,90.65 44.95,90.4 44.95,88.85 44.7,88.6 43.35,88.6 42.9,89.05 37.85,89.05 37.6,89.3 37.6,90.7 36.9,91.4 35.85,91.4 35.75,91.5 35.75,91.8
N2245591 on TOP (solid shape): 30.1,16.32 12.1,16.32 12.1,13.32 48.1,13.32 48.1,6.32 12.1,6.32 12.1,3.32 27.5,3.32 27.5,1.32 10.1,1.32 10.1,8.32 46.1,8.32 46.1,11.32 10.1,11.32 10.1,18.32 28.1,18.32 28.1,25.32 30.1,25.32
N2245591 on BOTTOM (solid shape): 30.1,16.3 12.1,16.3 12.1,13.3 48.1,13.3 48.1,6.3 12.1,6.3 12.1,3.3 27.5,3.3 27.5,1.3 10.1,1.3 10.1,8.3 46.1,8.3 46.1,11.3 10.1,11.3 10.1,18.3 28.1,18.3 28.1,25.3 30.1,25.3

Small or netless copper shapes (teardrops, artwork), in the pictures only: 4 on TOP

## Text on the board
Ref Des/Silkscreen Bottom: J1 | 1 | 10 | 21 | 30 | J3 | J4 | 31 | 40 | 11 | 20 | J2 | DIO23 | DIO22 | DIO24 | DIO2 | DIO3 | DIO1 | DIO25 | DIO27 | DIO28 | DIO29 | DIO30 | DIO26 | DIO7 | DIO6 | DIO20 | DIO19 | DIO18 | BPRST | DIO9 | DIO8 | DIO15 | DIO12 | DIO11 | LPRST | DIO13 | DIO14 | DIO10 | DIO21 | DIO4 | DIO5 | TMS | TCK | DIO16 | DIO17
User.Comments: WCS042 B | E1   INITIAL VERSION                                     2017-08-09  2017-08-09 | A    Production Release Version                          2017-10-20  2017-10-20 | B    Production Release Version (Added DustBin Symbol)   2018-01-04  2018-01-04 | PANEL DRAWING
Ref Des/Silkscreen Top: WCS042 B | J1 | 10 | 1 | 21 | 30 | J3 | J4 | 40 | 31 | 20 | 11 | J2 | DIO3 | DIO22 | DIO2 | DIO24 | DIO23 | DIO13 | BTN-1 | DIO1 | DIO26 | DIO25 | DIO27 | DIO28 | DIO29 | DIO30 | DIO6 | Red: | LEDs | Green: | DIO7 | CC-ANTENNA-DK | Mount for: | Target In | XDS110 Out | BP | LP | DIO20 | DIO19 | DIO18 | BPRST | BTN-2 | DIO14 | VSENS | XDS110 | Power | Extern | Pwr | DIO15 | DIO8 | DIO11 | LPRST | DIO9 | DIO12 | DIO10 | DIO21 | DIO4 | DIO5 | DIO17 | DIO16 | TMS | TCK | RXD<< | TXD>> | RST | TDO | TDI | SWO | LAUNCHXL-CC1312R1 | Rev:B
DIMENSION: V-CUT | PROCESS NOTES: | 4. APPLY NON-CONDUCTIVE LPI SILKSCREEN OR EQUIVALENT PER THE ARTWORK. | CLASS 2 AND WORKMANSHIP SHALL CONFORM TO | 3. SOLDERMASK ARTWORK HAS ZERO (0) OVERSIZED PADS. | 5. ALL VIAS ARE TENTED. | 2. PLATE ALL EXPOSED AREAS WITH ELECTROLESS NICKEL IMMERSION GOLD. | CURRENT REV. COLOR OF MASK TO BE RED. | CERTIFICATE OF CONFORMANCE SHALL BE DELIVERED | 6. MAX. WARP & TWIST TO BE .0075 PER INCH. | 7. BOARD MUST BE ELECTRICALLY TESTED USING | 1. APPLY LPI SOLDERMASK OVER BARE COPPER (SMOBC), | LEAD FREE ASSEMBLY CAPABLE. BOARD MATERIAL | 8. 0.32MM TRACES ON LAYER 1 ARE 50 OHMS +/-10%. | 3. BOARD MATERIAL SHALL BE 180 Tg/340 Td ISOLA | 5. OVERALL BOARD THICKNESS TO BE1.6 MM | PROCESSES, MEASURED FROM COPPER TO COPPER. | 4. BOARD MATERIAL & CONSTRUCTION TO BE U.L. 94V-0 | 2. THE PWB SHALL BE FABRICATED TO IPC-6012, | 1. ALL DIMENSIONS ARE IN MM, UNLESS | FAB NOTES: | UL GUIDE NUMBER SHOULD BE MARKED ON THE FINISHED | OTHERWISE NOTED. | AND APPLIES AFTER ALL LAMINATION AND PLATING | SUPPLIED IPC-D-356 NETLIST. | IPC-A-600, CLASS 2. CURRENT REVISIONS. | SHALL MEET OR EXCEED IPC-4101B. RoHS | FR-370HR OR EQUIVALENT, RoHS COMPLIANT AND | THEY ARE REFERENCE TO LAYER 2 GROUND | WITH EACH LOT. | SOLDERMASK SHALL CONFORM TO IPC-SM-840. CLASS H. | FABRICATION VENDOR IS ALLOWED TO ADJUST THE COMPONENT SOLDERMASK | APPROVED AND MARKED ON THE FINISHED BOARD. | BOARD. | NICKEL:100 MICRO-INCHES MIN. GOLD:2-8 MICROINCHES MIN. | COLOR: WHITE. | PADS TO MEET THEIR TOOLING REQUIREMENTS.
XSECTION_CHART: L1: TOP CONDUCTOR - COPPER + PLATING 0.035 MM | *  DIELECTRIC - FR-4 0.175 MM (TOP PRIORITY) | L2: L2 PLANE - COPPER 0.035 MM | *  DIELECTRIC - FR-4 1.11 MM | L3: L3 PLANE - COPPER 0.035 MM | *  DIELECTRIC - FR-4 0.175 MM | L4: BOTTOM CONDUCTOR - COPPER + PLATING 0.035 MM | DESIGN CROSS SECTION CHART | ___________________________ | TOTAL THICKNESS 1.6 MM
PAGE_OUTLINE: 2018-01-04 | TA | PM | FABRICATION DRAWING | LAUNCHXL-CC1312R1 | CC1312R LaunchPad | WCS042 B | NONE | 1 OF 1
